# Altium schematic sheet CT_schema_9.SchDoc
size 405 x 220 mm
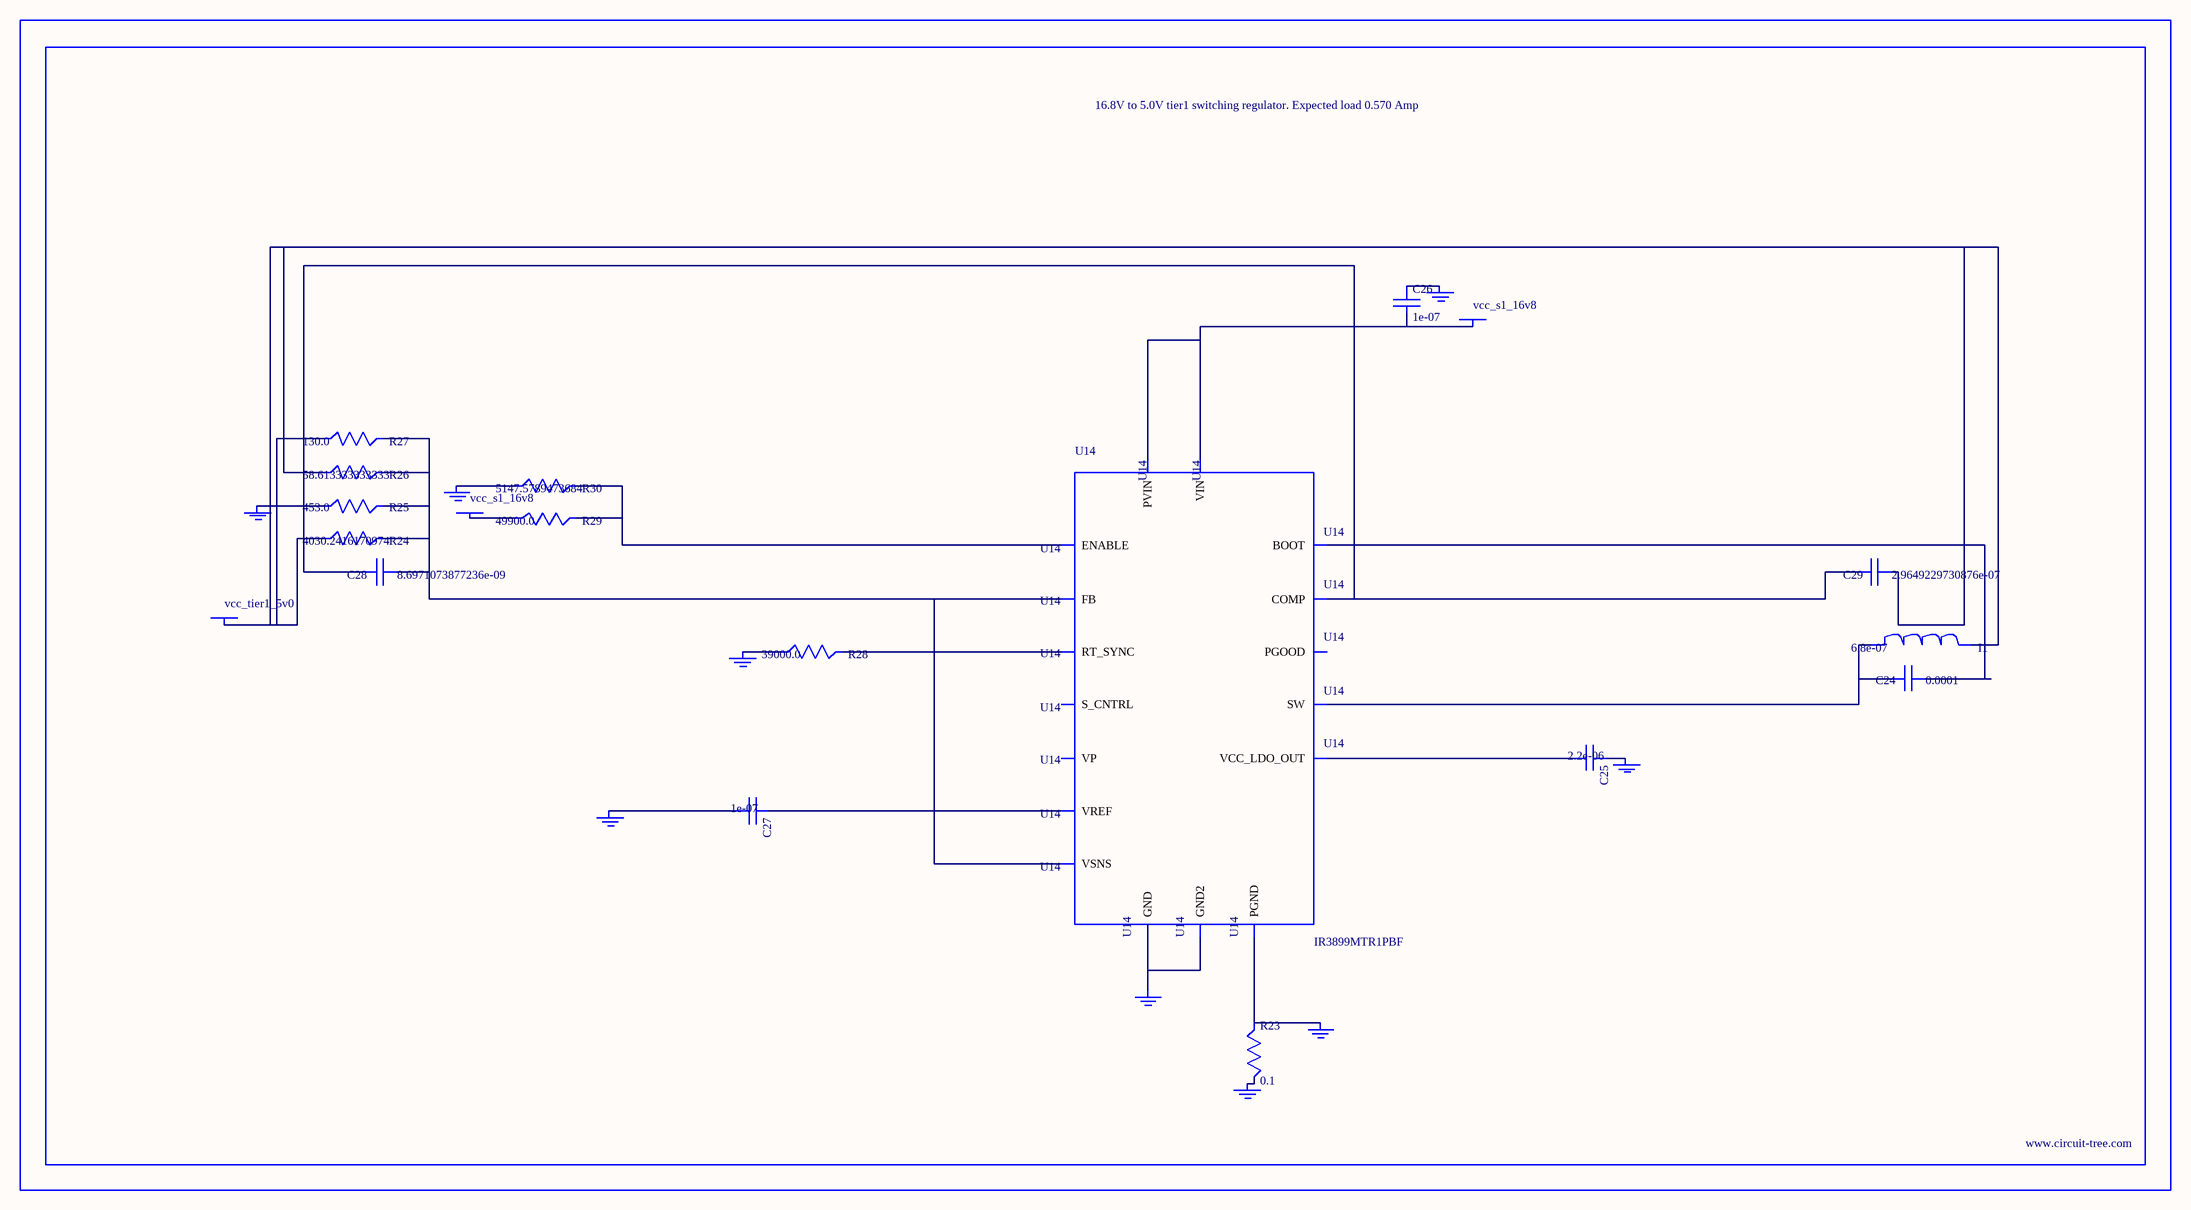
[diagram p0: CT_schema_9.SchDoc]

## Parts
BORDER8  (no value)
C24  0.0001  [C1210]
C25  2.2e-06  [C0603]
C26  1e-07  [C0402]
C27  1e-07  [C0402]
C28  8.6971073877236e-09  [R0603]
C29  2.9649229730876e-07  [R0603]
GND_INSTANCE_8_0  (no value)
GND_INSTANCE_8_1  (no value)
GND_INSTANCE_8_2  (no value)
GND_INSTANCE_8_3  (no value)
GND_INSTANCE_8_4  (no value)
GND_INSTANCE_8_5  (no value)
GND_INSTANCE_8_6  (no value)
GND_INSTANCE_8_7  (no value)
GND_INSTANCE_8_8  (no value)
I1  6.8e-07  [IND25X25CZ]
POWER_INSTANCE_8_0  vcc_s1_16v8
POWER_INSTANCE_8_1  vcc_s1_16v8
POWER_INSTANCE_8_2  vcc_tier1_5v0
R23  0.1  [R0603]
R24  4030.2416170974  [R0603]
R25  453.0  [R0603]
R26  58.613333333333  [R0603]
R27  130.0  [R0603]
R28  39000.0  [R0603]
R29  49900.0  [R0603]
R30  5147.5789473684  [R0603]
U14  IR3899MTR1PBF  [IR3899MTR1PBF]

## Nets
NetC24_1: C24.1 U14.14(BOOT)
NetC24_2: C24.2 I1.1 U14.12(SW)
NetC25_1: C25.1 GND_INSTANCE_8_4.0(GND)
NetC25_2: C25.2 U14.10(VCC_LDO_OUT)
NetC26_1: C26.1 GND_INSTANCE_8_3.0(GND)
NetC26_2: C26.2 POWER_INSTANCE_8_0.0(PWR) U14.9(VIN) U14.13(PVIN)
NetC27_1: C27.1 U14.2(VREF)
NetC27_2: C27.2 GND_INSTANCE_8_1.0(GND)
NetC28_1: C28.1 R24.2 R25.2 R26.2 R27.2 U14.1(FB) U14.8(VSNS)
NetC28_2: C28.2 C29.2 U14.3(COMP)
NetC29_1: C29.1 I1.2 POWER_INSTANCE_8_2.0(PWR) R24.1 R26.1 R27.1
NetGND_INSTANCE_8_0_0: GND_INSTANCE_8_0.0(GND) R25.1
NetGND_INSTANCE_8_2_0: GND_INSTANCE_8_2.0(GND) R28.1
NetGND_INSTANCE_8_5_0: GND_INSTANCE_8_5.0(GND) R23.2
NetGND_INSTANCE_8_6_0: GND_INSTANCE_8_6.0(GND) R23.1 U14.11(PGND)
NetGND_INSTANCE_8_7_0: GND_INSTANCE_8_7.0(GND) R30.1
NetGND_INSTANCE_8_8_0: GND_INSTANCE_8_8.0(GND) U14.4(GND) U14.17(GND2)
NetPOWER_INSTANCE_8_1_0: POWER_INSTANCE_8_1.0(PWR) R29.1
NetR28_2: R28.2 U14.5(RT_SYNC)
NetR29_2: R29.2 R30.2 U14.15(ENABLE)

Not connected (* = marked no-connect by the designer): U14 6(S_CNTRL) 7(PGOOD) 16(VP)

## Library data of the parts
BORDER8 = BORDER_PAGE8
C24 = GRM32ER61A107ME20L
C25 = C0603C225K8RACTU
C26 C27 = C0402C104K3RACTU
C28 = C28
C29 = C29
GND_INSTANCE_8_0-GND_INSTANCE_8_8 = GND
I1 = IHLP2525CZERR68M01
POWER_INSTANCE_8_0-POWER_INSTANCE_8_2 = PWR
R23 = ERJ-3RSFR10V
R24 = R24
R25 = ERJ-3EKF4530V
R26 = R26
R27 = RC0603JR-07130RL
R28 = RC0603JR-0739KL
R29 = RC0603FR-0749K9
R30 = R30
